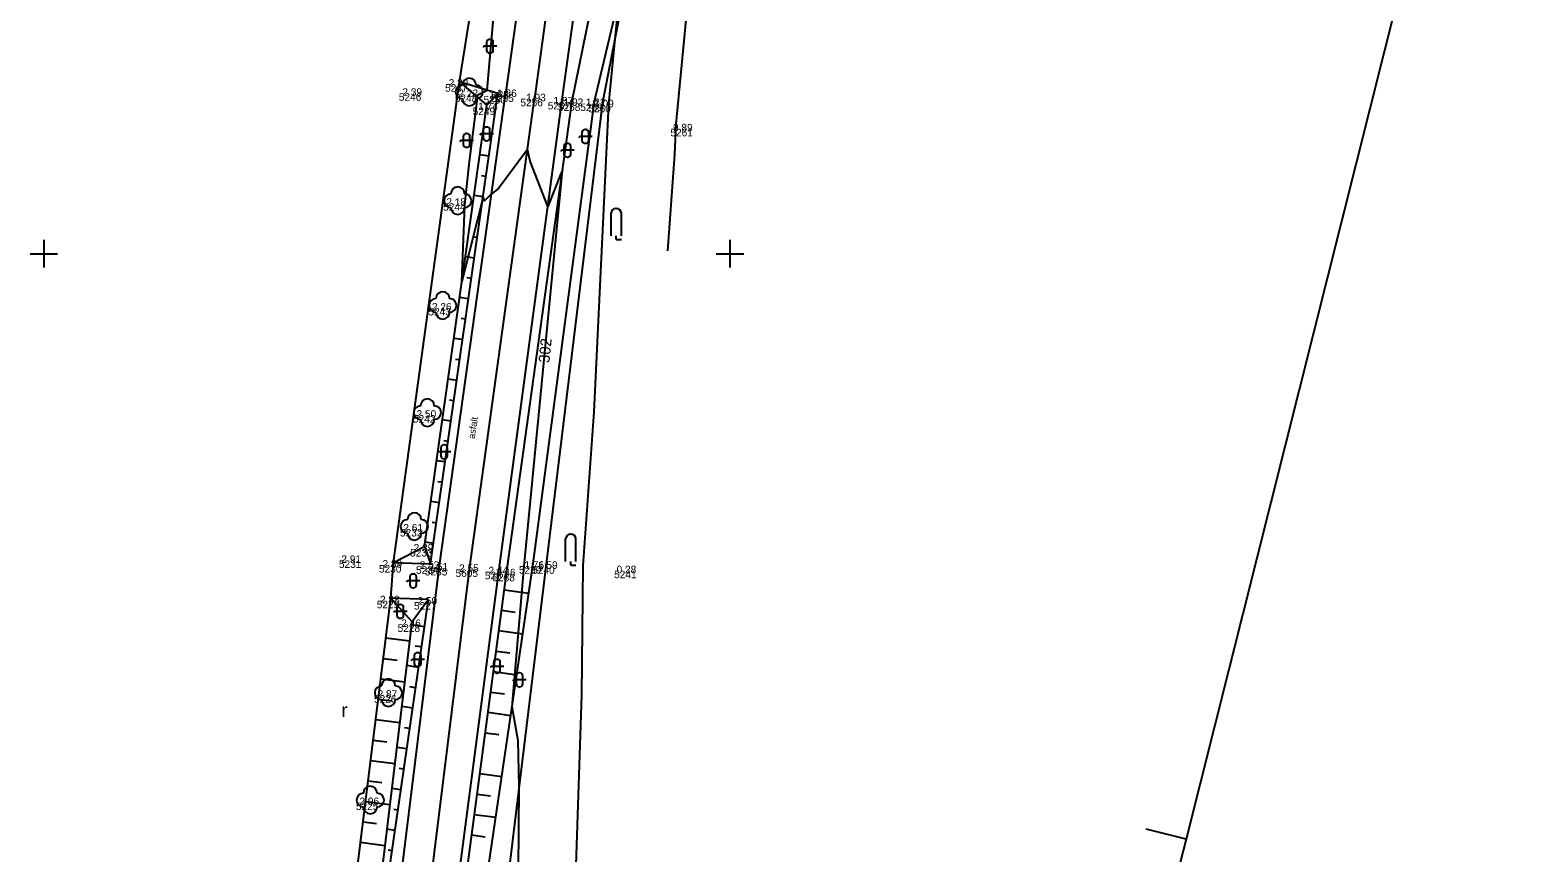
# Model space of a CAD drawing. Extents: x -740053 to -737517, y -1033516 to -1032488.
# Drawn here: x -739001 to -738891.1, y -1033143.6 to -1033083.7 of the extents above; entities that cross this region are included whole.
import ezdxf

# ---------------------------------------------------------------- set-up
doc = ezdxf.new("R2010")
doc.units = 0
for name, color, linetype in [('bod-cislo', 7, 'Continuous'), ('bod-oznac', 7, 'Continuous'), ('bod-vyska', 7, 'Continuous'), ('bod-vyska100', 7, 'Continuous'), ('Contours', 7, 'Continuous'), ('Contours highlighted', 7, 'Continuous'), ('Contours text', 7, 'Continuous'), ('ctv-sit', 7, 'Continuous'), ('Hranice-zelene', 7, 'Continuous'), ('nazvy-bud-povr', 7, 'Continuous'), ('osa-komunikace', 7, 'Continuous'), ('Predmety bez rozlišeni', 7, 'Continuous'), ('silnice', 7, 'Continuous'), ('Technické šrafy', 7, 'Continuous'), ('Terenni-hrana', 7, 'Continuous'), ('Znacky-kultury', 7, 'Continuous')]:
    doc.layers.add(name, color=color, linetype=linetype)

# ---------------------------------------------------------------- blocks, each defined once
blk = doc.blocks.new('POINT_DISPLAY')
blk.add_line((0, 0), (0, 0))
blk = doc.blocks.new('p_strom')
for centre, start, end in [((-1, 0), 90, 270), ((0, 1), 0, 180), ((1, 0), 270, 90), ((0, -1), 180, 0)]:
    blk.add_arc(centre, 1, start, end)
at = {"rotation": -180}
blk.add_blockref('POINT_DISPLAY', (0, 0), dxfattribs=at)
blk = doc.blocks.new('p_orna')
blk.add_text('r', height=2).set_placement((0, 0))
blk = doc.blocks.new('p_neplod')
for p, q in [((-0.82, 0), (-0.99, -0.18)), ((1, 0), (-0.82, 0)), ((-0.49, 0.56), (-0.49, -0.55)), ((0.05, 1.01), (-0.04, 1.01)), ((0.5, -0.55), (0.5, 0.56)), ((-0.04, -1), (0.05, -1))]:
    blk.add_line(p, q)
for centre, start, end in [((-0.04, 0.56), 90, 180), ((0.05, 0.56), 0, 90), ((-0.04, -0.55), 180, 270), ((0.05, -0.55), 270, 0)]:
    blk.add_arc(centre, 0.45, start, end)
blk = doc.blocks.new('p_leslis')
for p, q in [((-0.05, 4.51), (0.05, 4.51)), ((-0.75, 0.5), (-0.75, 3.81)), ((0.75, 0.5), (0.75, 3.81)), ((0, 0), (0, 0.5)), ((0, 0), (0.75, 0))]:
    blk.add_line(p, q)
for centre, start, end in [((-0.05, 3.81), 90, 180), ((0.05, 3.81), 0, 90)]:
    blk.add_arc(centre, 0.7, start, end)
blk = doc.blocks.new('ctvsit')
for p, q in [((2, 0), (-2, 0)), ((0, -2), (0, 2))]:
    blk.add_line(p, q)

msp = doc.modelspace()

# ---------------------------------------------------------------- linework, layer by layer
at = {"layer": 'Contours'}
for points in [[(-738961.36, -1033148.92), (-738960.79, -1033132.13), (-738960.71, -1033122.73), (-738959.89, -1033111.53), (-738958.83, -1033089.1), (-738958.37, -1033084.36), (-738958.04, -1033081.23), (-738956.87, -1033074.6), (-738956.56, -1033068.03), (-738956.64, -1033066.3), (-738956.55, -1033065.15), (-738956.31, -1033062.1), (-738955.28, -1033051.32), (-738953.4, -1033036.59), (-738952.72, -1033032.22), (-738952.59, -1033031.39)], [(-738965.4, -1033144.93), (-738965.35, -1033138.79), (-738965.43, -1033135.49), (-738965.88, -1033133), (-738965, -1033122.77), (-738962.2, -1033093.95), (-738962.31, -1033094.12), (-738963.27, -1033096.57), (-738964.57, -1033093.26), (-738964.75, -1033092.4), (-738966.87, -1033095.24), (-738967.38, -1033095.65), (-738967.88, -1033096.14), (-738967.99, -1033095.89), (-738968.4, -1033097.5), (-738969.54, -1033102.03), (-738969.33, -1033096.47), (-738968.97, -1033093.29), (-738968.41, -1033088.66), (-738968.52, -1033088.49), (-738967.69, -1033088.09), (-738967.34, -1033083.93), (-738967.16, -1033081.95)]]:
    msp.add_lwpolyline(points, dxfattribs=at)
at = {"layer": 'Contours highlighted'}
msp.add_lwpolyline([(-738954.53, -1033099.8), (-738954.02, -1033092.78), (-738953.91, -1033090.56), (-738953.74, -1033088.8), (-738951.62, -1033066.49), (-738951.55, -1033063.9), (-738951.51, -1033062.39), (-738950.67, -1033045.63), (-738950.52, -1033037.17), (-738949.81, -1033032.09)], dxfattribs=at)
at = {"layer": 'Hranice-zelene'}
for p, q in [((-738959.27, -1033088.97), (-738956.46, -1033074.63)), ((-738963.36, -1033122.59), (-738959.27, -1033088.97)), ((-738966.46, -1033147.87), (-738963.36, -1033122.59))]:
    msp.add_line(p, q, dxfattribs=at)
at = {"layer": 'osa-komunikace'}
for p, q in [((-738960.56, -1033061.44), (-738964.22, -1033088.53)), ((-738968.96, -1033122.82), (-738964.22, -1033088.53)), ((-738971.96, -1033147.05), (-738968.96, -1033122.82))]:
    msp.add_line(p, q, dxfattribs=at)
at = {"layer": 'Predmety bez rozlišeni'}
for p, q in [((-738891.12, -1033040.82), (-738916.76, -1033142.64)), ((-738916.76, -1033142.64), (-738919.67, -1033141.91)), ((-738916.76, -1033142.64), (-738942.39, -1033244.46))]:
    msp.add_line(p, q, dxfattribs=at)
at = {"layer": 'silnice'}
for p, q in [((-738962.55, -1033061.18), (-738966.34, -1033088.22)), ((-738962.23, -1033088.76), (-738958.52, -1033061.83)), ((-738971.18, -1033122.71), (-738966.34, -1033088.22)), ((-738966.81, -1033122.99), (-738962.23, -1033088.76)), ((-738974.14, -1033146.78), (-738971.18, -1033122.71)), ((-738970.01, -1033147.38), (-738966.81, -1033122.99))]:
    msp.add_line(p, q, dxfattribs=at)
at = {"layer": 'Technické šrafy'}
for p, q in [((-738967.56, -1033092.89), (-738968.23, -1033092.8)), ((-738967.78, -1033094.38), (-738968.11, -1033094.33)), ((-738967.99, -1033095.86), (-738968.65, -1033095.77)), ((-738968.42, -1033098.83), (-738968.74, -1033098.79)), ((-738968.63, -1033100.32), (-738969.28, -1033100.22)), ((-738968.84, -1033101.8), (-738969.17, -1033101.76)), ((-738969.05, -1033103.29), (-738969.7, -1033103.19)), ((-738969.27, -1033104.77), (-738969.59, -1033104.73)), ((-738969.48, -1033106.26), (-738970.12, -1033106.17)), ((-738969.69, -1033107.74), (-738970.01, -1033107.7)), ((-738969.9, -1033109.23), (-738970.54, -1033109.14)), ((-738970.12, -1033110.71), (-738970.43, -1033110.67)), ((-738970.33, -1033112.2), (-738970.96, -1033112.11)), ((-738970.54, -1033113.68), (-738970.86, -1033113.64)), ((-738970.76, -1033115.17), (-738971.38, -1033115.08)), ((-738970.97, -1033116.65), (-738971.28, -1033116.61)), ((-738971.18, -1033118.14), (-738971.8, -1033118.05)), ((-738971.39, -1033119.62), (-738971.7, -1033119.58)), ((-738971.61, -1033121.11), (-738972.22, -1033121.02)), ((-738966.44, -1033124.49), (-738964.67, -1033124.73)), ((-738972.26, -1033127.17), (-738973.2, -1033127.04)), ((-738966.64, -1033125.98), (-738965.65, -1033126.11)), ((-738975.07, -1033127.99), (-738973.34, -1033128.2)), ((-738966.84, -1033127.46), (-738965.1, -1033127.7)), ((-738972.48, -1033128.65), (-738972.93, -1033128.59)), ((-738967.04, -1033128.95), (-738966.05, -1033129.08)), ((-738975.26, -1033129.48), (-738974.26, -1033129.6)), ((-738972.69, -1033130.14), (-738973.56, -1033130.01)), ((-738975.44, -1033130.97), (-738973.7, -1033131.18)), ((-738967.24, -1033130.44), (-738965.54, -1033130.67)), ((-738975.63, -1033132.45), (-738974.64, -1033132.58)), ((-738972.91, -1033131.62), (-738973.32, -1033131.56)), ((-738967.44, -1033131.93), (-738966.44, -1033132.06)), ((-738973.12, -1033133.11), (-738973.92, -1033132.99)), ((-738967.63, -1033133.41), (-738965.97, -1033133.63)), ((-738975.81, -1033133.94), (-738974.06, -1033134.16)), ((-738973.34, -1033134.59), (-738973.72, -1033134.54)), ((-738976, -1033135.43), (-738975.01, -1033135.55)), ((-738967.83, -1033134.9), (-738966.84, -1033135.03)), ((-738976.19, -1033136.92), (-738974.42, -1033137.14)), ((-738973.55, -1033136.08), (-738974.28, -1033135.97)), ((-738973.76, -1033137.56), (-738974.11, -1033137.51)), ((-738968.23, -1033137.87), (-738966.63, -1033138.09)), ((-738976.37, -1033138.41), (-738975.38, -1033138.53)), ((-738973.98, -1033139.05), (-738974.64, -1033138.95)), ((-738976.56, -1033139.9), (-738974.78, -1033140.12)), ((-738968.43, -1033139.36), (-738967.44, -1033139.49)), ((-738974.19, -1033140.53), (-738974.5, -1033140.49)), ((-738968.63, -1033140.85), (-738967.07, -1033141.05)), ((-738976.74, -1033141.38), (-738975.75, -1033141.51)), ((-738974.41, -1033142.02), (-738975, -1033141.93)), ((-738968.83, -1033142.33), (-738967.83, -1033142.47)), ((-738976.93, -1033142.87), (-738975.14, -1033143.1)), ((-738974.62, -1033143.5), (-738974.9, -1033143.46))]:
    msp.add_line(p, q, dxfattribs=at)
at = {"layer": 'Terenni-hrana'}
for p, q in [((-738961.49, -1033088.87), (-738958.57, -1033074.49)), ((-738959.88, -1033088.88), (-738956.46, -1033074.63)), ((-738969.71, -1033087.47), (-738968.74, -1033081.35)), ((-738974.53, -1033122.5), (-738969.71, -1033087.47)), ((-738969.71, -1033087.47), (-738967.72, -1033089.17)), ((-738966.91, -1033088.33), (-738969.71, -1033087.47)), ((-738971.82, -1033122.59), (-738966.91, -1033088.33)), ((-738967.72, -1033089.17), (-738966.91, -1033088.33)), ((-738972.26, -1033121.33), (-738967.72, -1033089.17)), ((-738966.26, -1033123.13), (-738961.49, -1033088.87)), ((-738964.35, -1033122.58), (-738959.88, -1033088.88)), ((-738974.53, -1033122.5), (-738972.26, -1033121.33)), ((-738972.26, -1033121.33), (-738971.82, -1033122.59)), ((-738974.71, -1033125.1), (-738974.53, -1033122.5)), ((-738974.53, -1033122.5), (-738971.82, -1033122.59)), ((-738968.05, -1033147.75), (-738964.35, -1033122.58)), ((-738969.62, -1033148.28), (-738966.26, -1033123.13)), ((-738977.3, -1033145.85), (-738974.71, -1033125.1)), ((-738975.05, -1033146.47), (-738971.98, -1033125.2)), ((-738971.98, -1033125.2), (-738974.71, -1033125.1)), ((-738973.17, -1033126.82), (-738974.71, -1033125.1)), ((-738971.98, -1033125.2), (-738973.17, -1033126.82)), ((-738975.53, -1033146.36), (-738973.17, -1033126.82))]:
    msp.add_line(p, q, dxfattribs=at)

# ---------------------------------------------------------------- block references
at = {"layer": 'bod-oznac'}
for p in [(-738969.71, -1033087.47), (-738973.08, -1033088.13), (-738969, -1033088.22), (-738966.91, -1033088.33), (-738966.34, -1033088.22), (-738964.22, -1033088.53), (-738967.72, -1033089.17), (-738962.23, -1033088.76), (-738961.49, -1033088.87), (-738959.88, -1033088.88), (-738959.27, -1033088.97), (-738953.37, -1033090.72), (-738969.84, -1033096.14), (-738970.93, -1033103.77), (-738972.05, -1033111.58), (-738973, -1033119.87), (-738972.26, -1033121.33), (-738977.53, -1033122.16), (-738974.53, -1033122.5), (-738971.82, -1033122.59), (-738964.35, -1033122.58), (-738963.36, -1033122.59), (-738971.18, -1033122.71), (-738968.96, -1033122.82), (-738966.81, -1033122.99), (-738966.26, -1033123.13), (-738957.47, -1033122.91), (-738974.71, -1033125.1), (-738971.98, -1033125.2), (-738973.17, -1033126.82), (-738974.89, -1033131.98), (-738976.21, -1033139.8)]:
    msp.add_blockref('POINT_DISPLAY', p, dxfattribs=at)
at = {"layer": 'ctv-sit', "xscale": 0.5, "yscale": 0.5, "rotation": 180}
for p in [(-739000, -1033100), (-738950, -1033100)]:
    msp.add_blockref('ctvsit', p, dxfattribs=at)
at = {"layer": 'Znacky-kultury', "xscale": 0.5, "yscale": 0.5}
for name, p in [('p_neplod', (-738967.5, -1033084.89)), ('p_strom', (-738969, -1033088.22)), ('p_neplod', (-738967.74, -1033091.28)), ('p_neplod', (-738969.2, -1033091.75)), ('p_neplod', (-738960.54, -1033091.46)), ('p_neplod', (-738961.85, -1033092.47)), ('p_strom', (-738969.84, -1033096.14)), ('p_leslis', (-738958.29, -1033098.96)), ('p_strom', (-738970.93, -1033103.77)), ('p_strom', (-738972.05, -1033111.58)), ('p_neplod', (-738970.83, -1033114.44)), ('p_strom', (-738973, -1033119.87)), ('p_leslis', (-738961.6, -1033122.68)), ('p_neplod', (-738973.09, -1033123.84)), ('p_neplod', (-738974.03, -1033126.06)), ('p_neplod', (-738972.76, -1033129.57)), ('p_neplod', (-738966.99, -1033130.06)), ('p_strom', (-738974.89, -1033131.98)), ('p_neplod', (-738965.34, -1033131.05)), ('p_orna', (-738978.32, -1033133.75)), ('p_strom', (-738976.21, -1033139.8))]:
    msp.add_blockref(name, p, dxfattribs=at)

# ---------------------------------------------------------------- texts
at = {"layer": 'bod-cislo'}
for s, p in [('5246', (-738974.13, -1033088.86)), ('5247', (-738970.76, -1033088.2)), ('5248', (-738970.05, -1033088.95)), ('5250', (-738967.96, -1033089.06)), ('5255', (-738967.39, -1033088.95)), ('5249', (-738968.75, -1033089.9)), ('5256', (-738965.27, -1033089.26)), ('5257', (-738963.28, -1033089.49)), ('5258', (-738962.54, -1033089.6)), ('5259', (-738960.91, -1033089.61)), ('5260', (-738960.32, -1033089.7)), ('5261', (-738954.34, -1033091.45)), ('5244', (-738970.9, -1033096.87)), ('5243', (-738971.98, -1033104.5)), ('5242', (-738973.1, -1033112.31)), ('5232', (-738974.05, -1033120.6)), ('5233', (-738973.31, -1033122.06)), ('5231', (-738978.5, -1033122.89)), ('5230', (-738975.58, -1033123.23)), ('5234', (-738972.88, -1033123.32)), ('5235', (-738972.23, -1033123.44)), ('5605', (-738970, -1033123.55)), ('5237', (-738967.86, -1033123.72)), ('5238', (-738967.31, -1033123.86)), ('5239', (-738965.38, -1033123.31)), ('5240', (-738964.41, -1033123.32)), ('5241', (-738958.44, -1033123.64)), ('5229', (-738975.74, -1033125.83)), ('5227', (-738973.03, -1033125.93)), ('5228', (-738974.22, -1033127.55)), ('5226', (-738975.94, -1033132.71)), ('5225', (-738977.26, -1033140.53))]:
    msp.add_text(s, height=0.55, dxfattribs=at).set_placement(p)
at = {"layer": 'bod-vyska'}
for s, p in [('2 39', (-738970.5, -1033087.84)), ('2 39', (-738973.87, -1033088.5)), ('2 22', (-738969.79, -1033088.59)), ('1 85', (-738967.54, -1033088.7)), ('1 86', (-738966.97, -1033088.59)), ('1 93', (-738964.85, -1033088.9)), ('1 87', (-738962.86, -1033089.13)), ('1 74', (-738968.35, -1033089.54)), ('1 92', (-738962.12, -1033089.24)), ('1 22', (-738960.51, -1033089.25)), ('1 09', (-738959.9, -1033089.34)), ('9 89', (-738954.15, -1033091.09)), ('2 18', (-738970.67, -1033096.51)), ('2 26', (-738971.72, -1033104.14)), ('2 50', (-738972.84, -1033111.95)), ('2 61', (-738973.8, -1033120.24)), ('2 39', (-738973.05, -1033121.7)), ('2 91', (-738978.32, -1033122.53)), ('2 89', (-738975.32, -1033122.87)), ('2 53', (-738972.61, -1033122.96)), ('2 51', (-738971.97, -1033123.08)), ('2 55', (-738969.74, -1033123.18)), ('1 76', (-738964.98, -1033122.95)), ('1 59', (-738963.99, -1033122.96)), ('2 44', (-738967.6, -1033123.36)), ('2 46', (-738967.05, -1033123.5)), ('0 28', (-738958.26, -1033123.28)), ('2 88', (-738975.5, -1033125.47)), ('2 59', (-738972.77, -1033125.57)), ('2 46', (-738973.96, -1033127.19)), ('2 87', (-738975.68, -1033132.35)), ('2 96', (-738977, -1033140.17))]:
    msp.add_text(s, height=0.55, dxfattribs=at).set_placement(p)
at = {"layer": 'bod-vyska100'}
for s, p in [('302 39', (-738969.88, -1033087.5)), ('302 39', (-738973.25, -1033088.16)), ('302 22', (-738969.17, -1033088.25)), ('301 85', (-738967.07, -1033088.36)), ('301 86', (-738966.5, -1033088.25)), ('301 93', (-738964.38, -1033088.56)), ('301 74', (-738967.88, -1033089.2)), ('301 87', (-738962.39, -1033088.79)), ('301 92', (-738961.65, -1033088.9)), ('301 22', (-738960.04, -1033088.91)), ('301 09', (-738959.43, -1033089)), ('299 89', (-738953.54, -1033090.75)), ('302 18', (-738970.01, -1033096.17)), ('302 26', (-738971.1, -1033103.8)), ('302 50', (-738972.22, -1033111.61)), ('302 61', (-738973.17, -1033119.9)), ('302 39', (-738972.43, -1033121.36)), ('302 91', (-738977.7, -1033122.19)), ('302 89', (-738974.7, -1033122.53)), ('302 53', (-738971.99, -1033122.62)), ('301 76', (-738964.51, -1033122.61)), ('301 59', (-738963.52, -1033122.62)), ('302 51', (-738971.35, -1033122.74)), ('302 55', (-738969.12, -1033122.85)), ('302 44', (-738966.98, -1033123.02)), ('302 46', (-738966.43, -1033123.16)), ('300 28', (-738957.64, -1033122.94)), ('302 88', (-738974.88, -1033125.13)), ('302 59', (-738972.15, -1033125.23)), ('302 46', (-738973.34, -1033126.85)), ('302 87', (-738975.06, -1033132.01)), ('302 96', (-738976.38, -1033139.83))]:
    msp.add_text(s, height=0.05, dxfattribs=at).set_placement(p)
at = {"layer": 'Contours text'}
msp.add_text('302', height=0.8, rotation=84.4353, dxfattribs=at).set_placement((-738963.16, -1033107.98))
at = {"layer": 'nazvy-bud-povr'}
msp.add_text('asfalt', height=0.5, rotation=81.2244, dxfattribs=at).set_placement((-738968.6, -1033113.51))

doc.saveas('drawing.dxf')
